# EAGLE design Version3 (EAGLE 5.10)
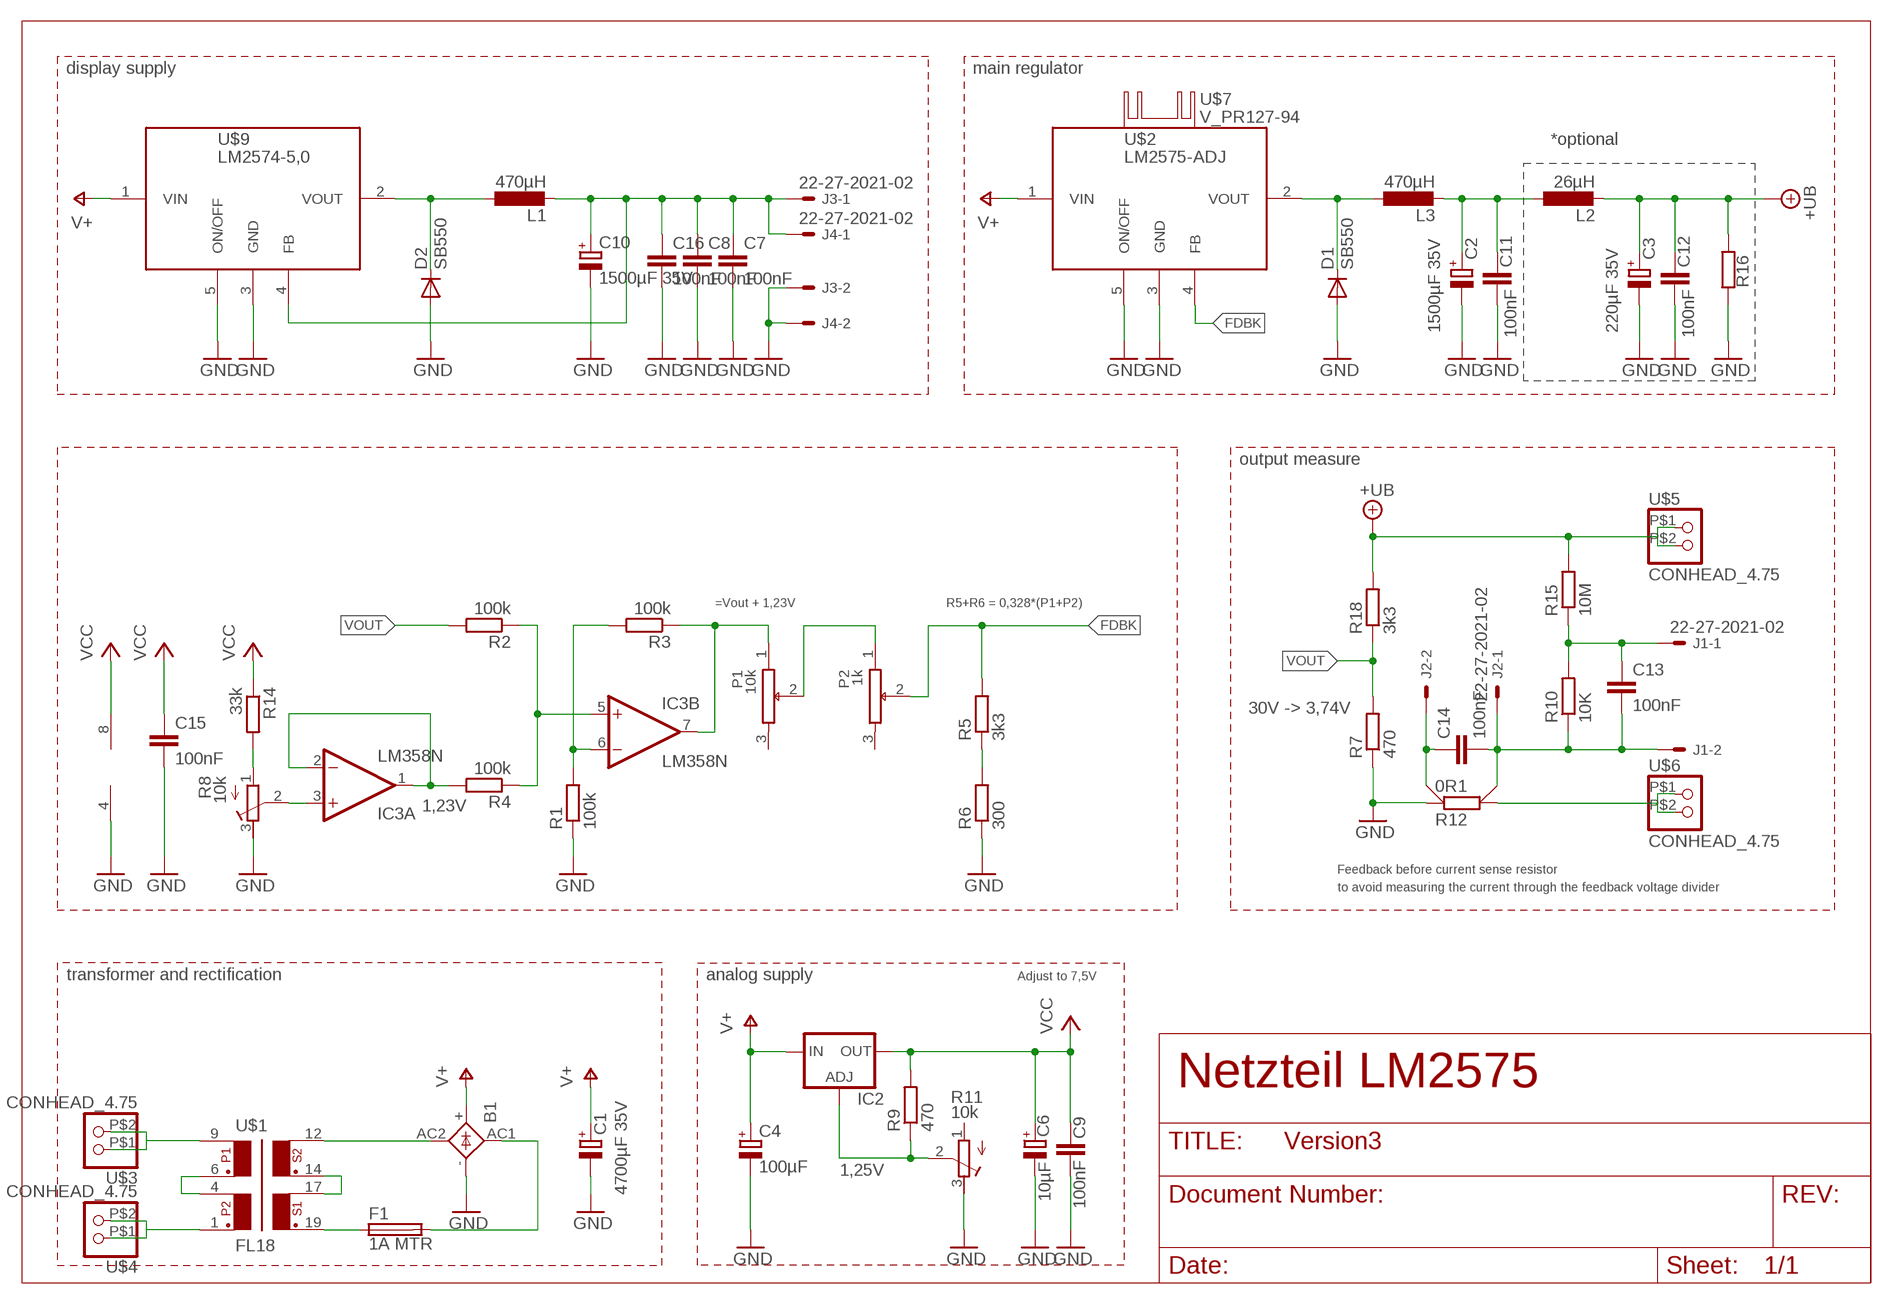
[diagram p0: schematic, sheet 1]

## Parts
B1  FB100  [FB100]
C1  4700µF 35V  CPOL-EUE7.5-18  [E7,5-18]
C2  1500µF 35V  CPOL-EUE5-13  [E5-13]
C3  220µF 35V  CPOL-EUE3.5-8  [E3,5-8]
C4  100µF  CPOL-EUE2.5-7  [E2,5-7]
C6  10µF  CPOL-EUE2-5  [E2-5]
C7  100nF  C-EU025-025X050  [C025-025X050]
C8  100nF  C-EU025-025X050  [C025-025X050]
C9  100nF  C-EU025-025X050  [C025-025X050]
C10  1500µF 35V  CPOL-EUE2.5-7  [E2,5-7]
C11  100nF  C-EU025-025X050  [C025-025X050]
C12  100nF  C-EU025-025X050  [C025-025X050]
C13  100nF  C-EU025-025X050  [C025-025X050]
C14  100nF  C-EU025-025X050  [C025-025X050]
C15  100nF  C-EU050-030X075  [C050-030X075]
C16  100nF  C-EU025-025X050  [C025-025X050]
D1  SB550  SB320  [DO201-15]
D2  SB550  SB320  [DO201-15]
F1  1A MTR  FUSESH22,5A  [SH22,5A]
IC2  LM317L  [317L]
IC3  LM358N  [DIL08]
J1  22-27-2021-02  [6410-02]
J2  22-27-2021-02  [6410-02]
J3  22-27-2021-02  [6410-02]
J4  22-27-2021-02  [6410-02]
L1  470µH  L-EUL-11PHC  [L-11PHC]
L2  26µH  L-EUFED26  [FED26]
L3  470µH  L-EUKM5  [INDUCTOR_KM5]
P1  10k  POTH_1  [POTH_1]
P2  1k  POTH_1  [POTH_1]
R1  100k  R-EU_0207/10_WP  [0207/10_WP]
R2  100k  R-EU_0207/10_WP  [0207/10_WP]
R3  100k  R-EU_0207/10_WP  [0207/10_WP]
R4  100k  R-EU_0207/10_WP  [0207/10_WP]
R5  3k3  R-EU_0207/10_WP  [0207/10_WP]
R6  300  R-EU_0207/10_WP  [0207/10_WP]
R7  470  R-EU_0207/10_WP  [0207/10_WP]
R8  10k  R-TRIMM64W  [RTRIM64W]
R9  470  R-EU_0207/10_WP  [0207/10_WP]
R10  10K  R-EU_0207/10_WP  [0207/10_WP]
R11  10k  R-TRIMM64W  [RTRIM64W]
R12  0R1  R_EU_S  [0617/22_D]
R14  33k  R-EU_0207/10_WP  [0207/10_WP]
R15  10M  R-EU_0207/10_WP  [0207/10_WP]
R16  R-EU_0309/12_WP  [0309/12_WP]
R18  3k3  R-EU_0207/10_WP  [0207/10_WP]
U$1  FL18  [FL18]
U$2  LM2575-ADJ  LM2575S  [TO220-51]
U$3  CONHEAD_4.75  [CONHEAD_4.75]
U$4  CONHEAD_4.75  [CONHEAD_4.75]
U$5  CONHEAD_4.75  [CONHEAD_4.75]
U$6  CONHEAD_4.75  [CONHEAD_4.75]
U$7  V_PR127-94  [V_PR127/94]
U$9  LM2574-5,0  LM2575S  [TO220-51]

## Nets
+UB: C3.+ C12.1 L2.P$2 R15.2 R16.2 R18.2 U$5.P$1 U$5.P$2
FDBK: P2.2 R5.2 U$2.4(FB)
GND: B1.- C1.- C2.- C3.- C4.- C6.- C7.2 C8.2 C9.2 C10.- C11.2 C12.2 C15.2 C16.2 D1.A D2.A IC3.4(P:V-) J3.2 J4.2 R1.1 R6.1 R7.1 R8.3(A) R11.3(A) R12.1 R16.1 U$2.3(GND) U$2.5(ON/OFF) U$9.3(GND) U$9.5(ON/OFF)
IN-: IC3.6(B:-IN) R1.2 R3.2
N$1: D1.C L3.P$1 U$2.2(VOUT)
N$2: F1.1 U$1.19
N$3: C2.+ C11.1 L2.P$1 L3.P$2
N$4: IC3.1(A:OUT) IC3.2(A:-IN) R4.2
N$5: D2.C L1.P$1 U$9.2(VOUT)
N$6: B1.AC1 F1.2
N$7: B1.AC2 U$1.12
N$8: U$1.4 U$1.6
N$9: U$1.14 U$1.17
N$10: U$1.9 U$3.P$1 U$3.P$2
N$11: U$1.1 U$4.P$1 U$4.P$2
N$12: P1.2 P2.1
N$13: R5.1 R6.2
N$14: IC3.5(B:+IN) R2.1 R4.1
N$15: R12.2 U$6.P$1 U$6.P$2
N$16: C13.1 J1.1 R10.2 R15.1
N$17: IC2.1(ADJ) R9.1 R11.2(S)
N$19: C13.2 C14.2 J1.2 J2.1 R10.1 R12.P$2
N$20: R8.1(E) R14.2
N$23: C14.1 J2.2 R12.P$1
N$24: IC3.7(B:OUT) P1.1 R3.1
N$31: C7.1 C8.1 C10.+ C16.1 J3.1 J4.1 L1.P$2 U$9.4(FB)
N$32: IC3.3(A:+IN) R8.2(S)
V+: B1.+ C1.+ C4.+ IC2.3(IN) U$2.1(VIN) U$9.1(VIN)
VCC: C6.+ C9.1 C15.1 IC2.2(OUT) IC3.8(P:V+) R9.2 R14.1
VOUT: R2.2 R7.2 R18.1
Unconnected: P1.3 P2.3 R11.1(E)

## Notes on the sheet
- display supply | main regulator
- *optional
- output measure
- =Vout + 1,23V | R5+R6 = 0,328*(P1+P2)
- 30V -> 3,74V
- 1,23V
- Feedback before current sense resistor
- to avoid measuring the current through the feedback voltage divider
- transformer and rectification | analog supply | Adjust to 7,5V
- Netzteil LM2575
- 1,25V

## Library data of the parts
B1 = rectifier:FB100: FAGOR RECTIFIER grid 1 x 10,2 x 7,5 mm
C1-C4 C6 C10 = rcl:CPOL-EU: POLARIZED CAPACITOR, European symbol
C7-C9 C11-C16 = rcl:C-EU: CAPACITOR, European symbol
D1 D2 = diode:SB320: DIODE
F1 = fuse:FUSE: Fuse
IC2 = v-reg:LM317L: VOLTAGE REGULATOR
IC3 = linear:LM358: OP AMP also LM158; LM258; LM2904 Source: http://cache.national.com/ds/LM/LM158.pdf
J1-J4 = con-molex:22-?-02: CONNECTOR
L1 = rcl2:L-EU: INDUCTOR, European symbol
L2 L3 = rcl:L-EU: INDUCTOR, European symbol
P1 P2 = Pot1:POTH_1
R1-R7 R9 R10 R14 R15 R18 = rcl:R-EU_: RESISTOR, European symbol
R8 R11 = rcl2:R-TRIMM: Trimm resistor
R12 = rcl2:R_EU_S
R16 = rcl2:R-EU_: RESISTOR, European symbol
U$1 = trafo:FL18: TRANSFORMER 2 primary winding, 2 secondary windings BLOCK
U$2 U$9 = linear2:LM2575
U$3-U$6 = pinhead:CONHEAD_4.75
U$7 = heatsink:V_PR127-94

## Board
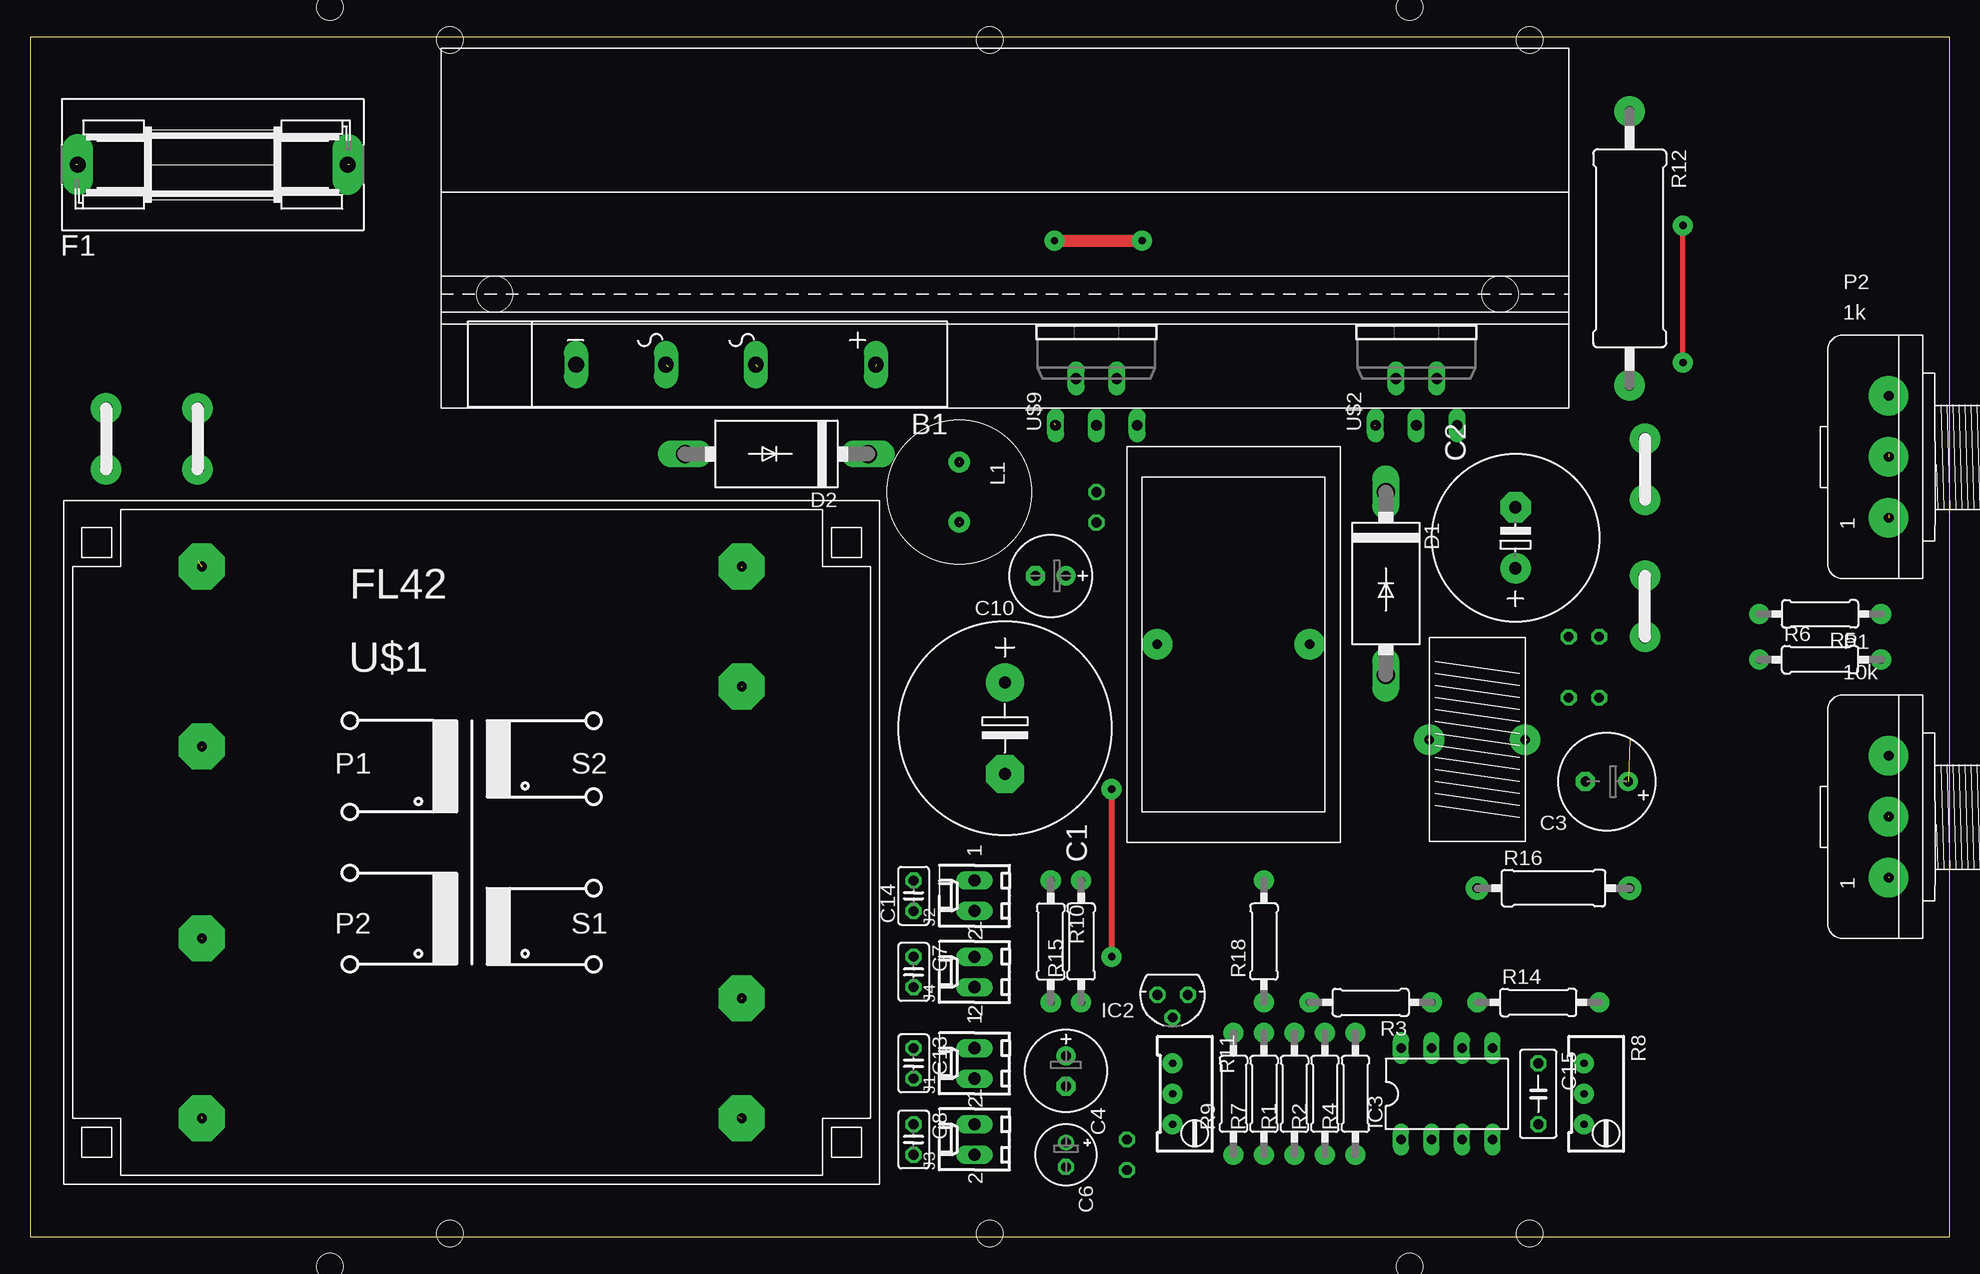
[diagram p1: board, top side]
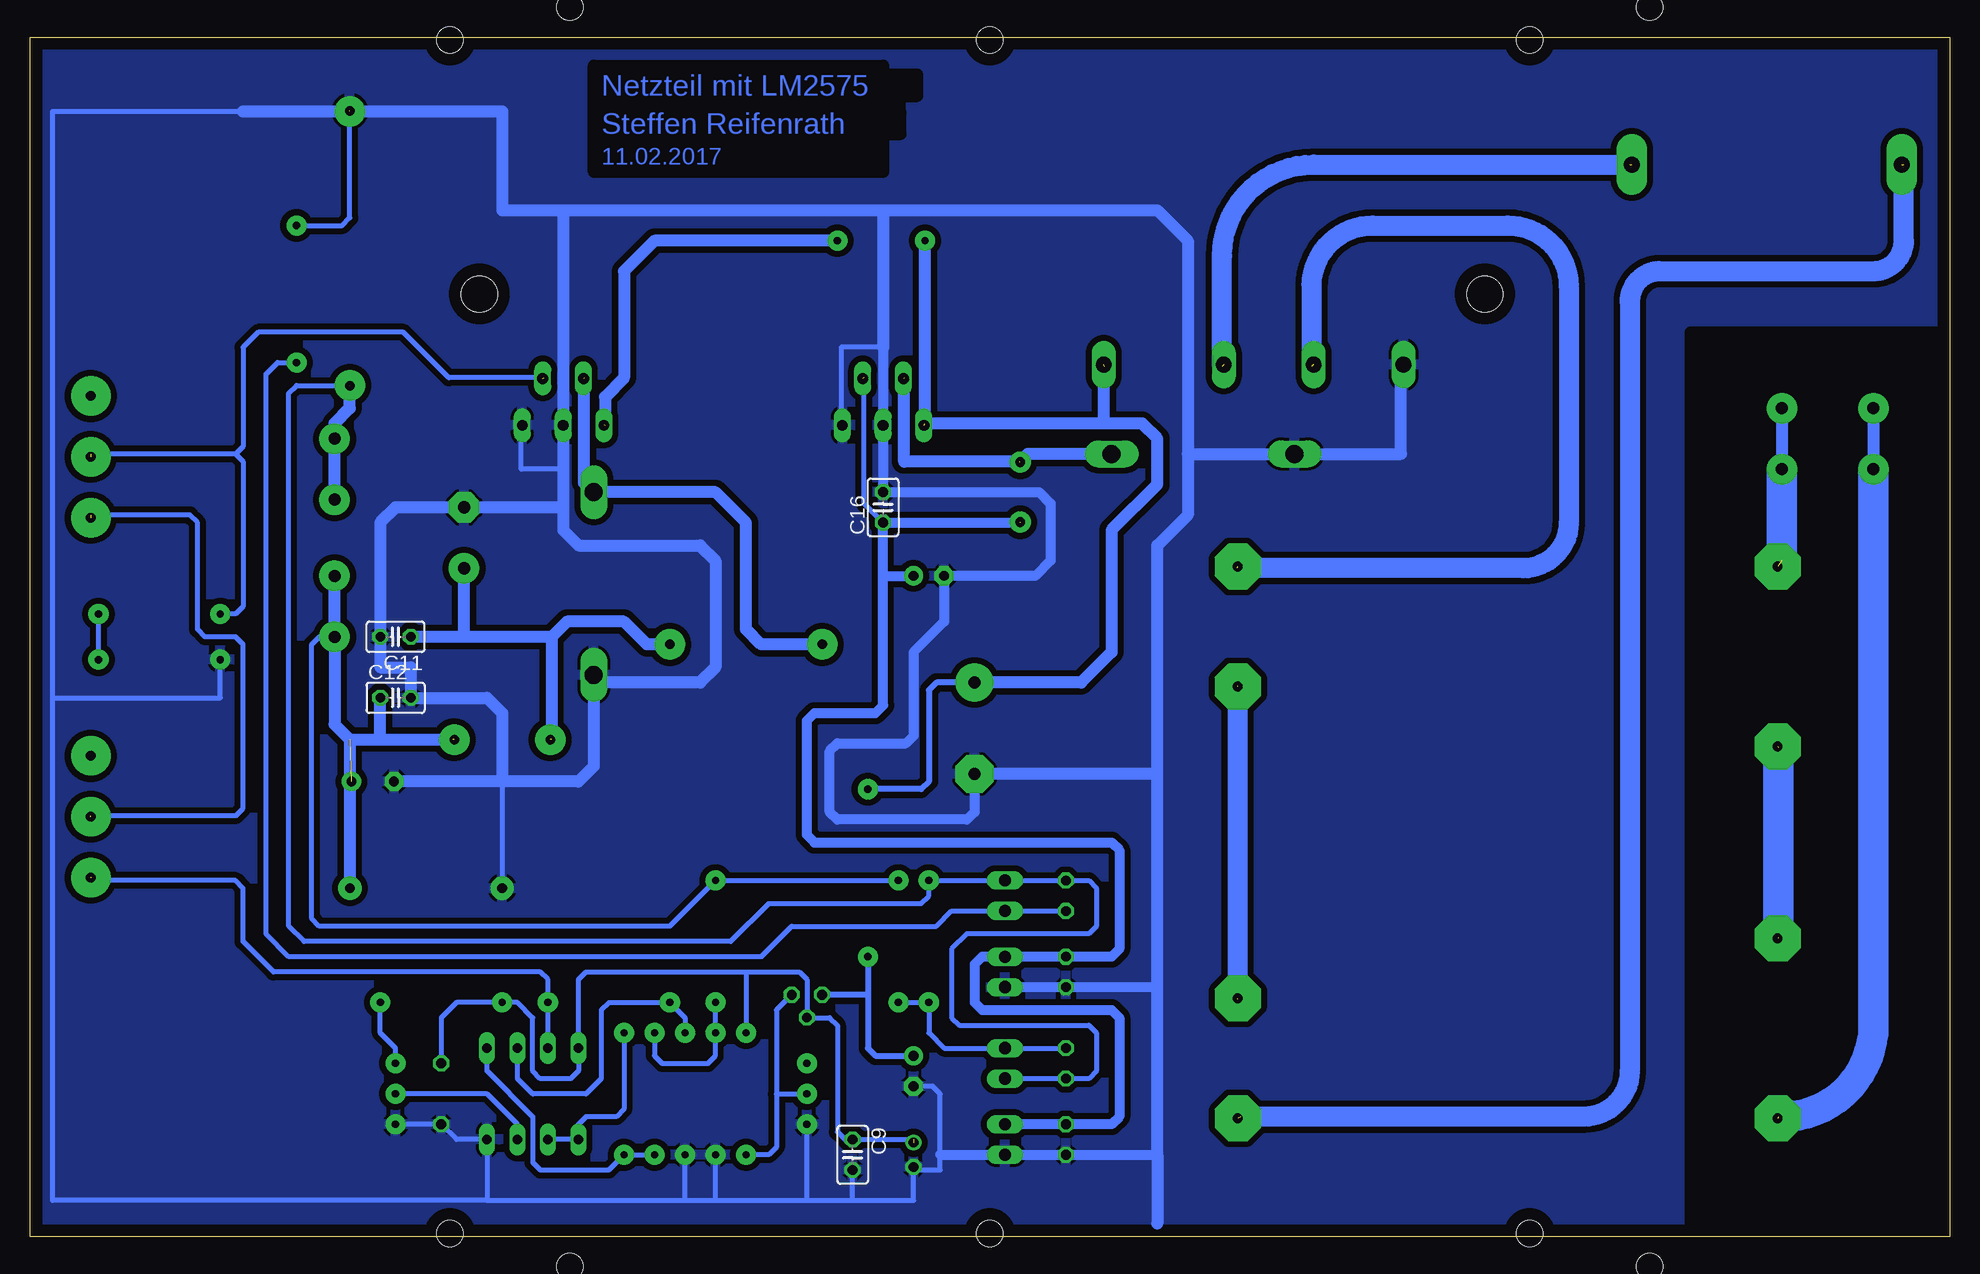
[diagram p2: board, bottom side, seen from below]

Size 160 x 100 mm. Coordinates in mm from the lower left corner, seen from the top.
Outline: 0,100 0,0 160,0 160,100 0,100
Copper layers (1*16): Top 0.035mm / dielectric 1.5mm / Bottom 0.035mm
Design rules "default": minimum track width 10mil, minimum drill 24mil, track to track 8mil, track to pad 8mil, pad to pad 8mil, via to via 8mil, smd to smd 8mil, copper to edge 40mil, drill to drill 8mil, minimum pad ring 10mil, minimum via ring 8mil, stop-mask expansion 4mil, vias tented up to drill 0mil, thermal gap 10mil
Holes 3 mm at 122.55,78.58 38.73,78.58
bRestrict: area 0,0.5 to 21.6,75.4; area 88.9,88.7 to 113,97.6

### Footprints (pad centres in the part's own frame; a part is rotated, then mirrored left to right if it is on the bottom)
FB100 = drill 1.321 long: + -14,0; - 10.994,0; AC1 -3.992,0; AC2 3.501,0
E7,5-18 = drill 1.016 pad 3.15 round: + -3.81,0 | drill 1.016 pad 3.15 octagon: - 3.81,0
E5-13 = drill 1.016 pad 2.54 round: + -2.54,0 | drill 1.016 pad 2.54 octagon: - 2.54,0
E3,5-8 = drill 0.813 pad 1.6 round: + -1.778,0 | drill 0.813 pad 1.6 octagon: - 1.778,0
E2,5-7 = drill 0.813 pad 1.6 round: + -1.27,0 | drill 0.813 pad 1.6 octagon: - 1.27,0
E2-5 = drill 0.813 pad 1.27 round: + -1.016,0 | drill 0.813 pad 1.27 octagon: - 1.016,0
C025-025X050 = drill 0.813 octagon: 1 -1.27,0; 2 1.27,0
C050-030X075 = drill 0.813 octagon: 1 -2.54,0; 2 2.54,0
DO201-15 = drill 1.499 long: A 7.62,0; C -7.62,0
SH22,5A = drill 1.321 pad 2.54 long: 1 -11.252,0; 2 11.252,0
317L = drill 0.813 octagon: 1 -1.27,0; 2 0,1.905; 3 1.27,0
DIL08 = drill 0.813 long: 1 -3.81,-3.81; 2 -1.27,-3.81; 3 1.27,-3.81; 4 3.81,-3.81; 5 3.81,3.81; 6 1.27,3.81; 7 -1.27,3.81; 8 -3.81,3.81
6410-02 = drill 1.016 long: 1 1.27,0; 2 -1.27,0
L-11PHC = drill 0.8 pad 1.778 round: P$1 -2.5,0; P$2 2.5,0
FED26 = drill 0.8 pad 2.54 round: P$1 0,4; P$2 0,-4
INDUCTOR_KM5 = drill 0.8 pad 2.54 round: P$1 0,6.35; P$2 0,-6.35
POTH_1 = drill 0.813 pad 3.302 round: 1 5.08,3.81; 2 0,3.81; 3 -5.08,3.81
0207/10_WP = drill 0.6 pad 1.676 round: 1 -5.08,0; 2 5.08,0
RTRIM64W = drill 0.61 pad 1.676 round: 1 1.27,-2.54; 2 1.27,0; 3 1.27,2.54
0617/22_D = drill 0.6 pad 2.54 round: 1 -11.43,0; 2 11.43,0 | drill 0.8 round: P$1 -11.455,0; P$2 11.455,0
0309/12_WP = drill 0.813 pad 1.93 round: 1 -6.35,0; 2 6.35,0
FL18 = drill 0.8 pad 3.81 octagon: 1 -22.5,-23; 4 -22.5,-8; 6 -22.5,8; 9 -22.5,23; 12 22.5,23; 14 22.5,13; 17 22.5,-13; 19 22.5,-23
TO220-51 = drill 0.9 long: 1 -3.4,-8.4; 2 -1.7,-4.5; 3 0,-8.4; 4 1.7,-4.5; 5 3.4,-8.4
CONHEAD_4.75 = drill 1 pad 2.54 round: P$1 -2.54,0; P$2 2.54,0
TEKO_KL = hole 2.2: 49.75,0; -49.75,0; -49.75,-45; 49.75,-45; 49.75,45; -49.75,45; 52.5,-55; -52.5,-55; -52.5,35; 52.5,35

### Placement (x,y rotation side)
B1  56.5,72.7 180 top
C1  81.27,42.38 270 top
C2  123.81,58.26 90 top
C3  131.44,37.94 180 top
C4  86.35,13.8 270 top
C6  86.35,6.82 270 top
C7  73.65,22.06 270 top
C8  73.65,8.09 270 top
C9  91.43,6.82 270 bottom
C10  85.08,55.08 180 top
C11  129.53,50 180 bottom
C12  129.53,44.92 0 bottom
C13  73.65,14.44 270 top
C14  73.65,28.41 90 top
C15  125.72,11.9 270 top
C16  88.89,60.8 90 bottom
D1  113.02,54.45 270 top
D2  62.22,65.24 180 top
F1  15.23,89.37 0 top
IC2  95.24,20.16 180 top
IC3  118.1,11.9 0 top
J1  78.73,14.44 90 top
J2  78.73,28.41 90 top
J3  78.73,8.09 90 top
J4  78.73,22.06 90 top
L1  77.46,62.06 270 top
L2  120.64,41.43 90 top
L3  100.32,49.37 90 top
P1  151.12,35 270 top
P2  151.12,65 270 top
R1  105.4,11.9 90 top
R2  107.94,11.9 90 top
R3  111.75,19.52 180 top
R4  110.48,11.9 90 top
R5  149.22,51.91 180 top
R6  149.22,48.09 0 top
R7  102.86,11.9 90 top
R8  130.8,11.9 180 top
R9  100.32,11.9 90 top
R10  85.08,24.6 270 top
R11  96.51,11.9 180 top
R12  133.34,82.38 270 top
R14  125.72,19.52 0 top
R15  87.62,24.6 90 top
R16  126.99,29.05 0 top
R18  102.86,24.6 90 top
U$1  36.82,32.86 0 top
U$2  115.56,76.03 0 top
U$3  13.96,66.51 270 top
U$4  6.34,66.51 270 top
U$5  134.61,52.54 90 top
U$6  134.61,63.97 270 top
U$7  34.28,69.05 0 top
U$8  [TEKO_KL]  80,50 270 top
U$9  88.89,76.03 0 top

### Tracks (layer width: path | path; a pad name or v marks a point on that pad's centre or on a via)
+UB  (2 unrouted)
  Bottom 0.406: R15.2 R18.2 106.67,25.87 135.88,25.87 136.51,26.5 136.51,49.37 135.88,50 U$5.P$1
  Bottom 1.016: 130.8,41.43 C12.1 | 130.8,41.43 124.77,41.43 | 133.34,41.43 130.8,41.43 | U$5.P$2 U$5.P$1 134.61,42.7 133.34,41.43 | 133.34,41.43 R16.2
FDBK  (2 unrouted)
  Bottom 0.406: 142.87,65.24 154.93,65.24 | 142.87,65.24 142.23,65.88 142.23,74.13 140.96,75.4 128.9,75.4 125.09,71.59 117.15,71.59 | 142.87,65.24 142.23,64.61 142.23,52.54 142.87,51.91 R5.2
GND
  Bottom 0.406: 92.38,67.78 92.38,74.13 88.89,74.13 | 142.23,93.81 158.11,93.81 158.11,44.92 | 158.11,44.92 158.11,3.01 121.91,3.01 | 121.91,3.01 105.4,3.01 | 105.4,3.01 102.86,3.01 | 102.86,3.01 95.24,3.01 | 95.24,3.01 91.43,3.01 | 91.43,3.01 86.35,3.01 86.35,5.55 84.13,5.55 84.13,6.82 84.13,11.9 84.76,12.53 C4.- | 121.91,3.01 IC3.4 124.45,8.09 C15.2 R8.3 | 102.86,3.01 R7.1 | 105.4,3.01 R1.1 | 95.24,3.01 R11.3 | 119.05,67.78 119.05,63.97 115.56,63.97 | 120.64,37.94 R16.1 | R6.1 144.13,44.92 158.11,44.92 | 91.43,3.01 C9.2
  Bottom 0.813: 66.03,6.82 C8.2 J3.2 84.13,6.82 | J4.2 C7.2 66.03,20.79 | 88.89,74.13 C16.2 75.87,62.06 74.92,61.11 74.92,56.35 76.19,55.08 C10.- 83.81,51.27 86.35,48.73 86.35,41.74 86.98,41.11 92.7,41.11 93.34,40.48 93.34,35.39 92.7,34.76 81.91,34.76 81.27,35.39 C1.-
  Bottom 1.016: 45.71,72.54 45.71,65.24 D2.A 63.49,65.24 | 63.49,65.24 63.49,60.16 66.03,57.62 66.03,38.57 | 63.49,65.24 63.49,83.02 66.03,85.56 88.89,85.56 | 88.89,85.56 88.89,74.13 | 66.03,38.57 C1.- | 115.56,85.56 88.89,85.56 | 115.56,85.56 120.64,85.56 120.64,93.81 R12.1 142.23,93.81 | 115.56,60.8 115.56,63.97 115.56,85.56 | 66.03,38.57 66.03,20.79 66.03,6.82 66.03,1.1 | 115.56,60.8 C2.- 129.53,60.8 130.8,59.52 C11.2 130.8,47.46 128.26,47.46 C12.2 121.91,44.92 120.64,43.65 120.64,37.94 | 115.56,60.8 115.56,58.89 114.29,57.62 104.13,57.62 102.86,56.35 102.86,47.46 104.13,46.19 113.02,46.19 | 120.64,37.94 114.29,37.94 113.02,39.2 113.02,46.19 | 120.64,37.94 129.85,37.94 | 113.02,46.19 D1.A
  pour Bottom (isolate 0.508): -1.28,-0.8 161.28,-0.8 161.28,100.8 -1.28,100.8
IN-
  Bottom 0.406: IC3.6 119.37,13.17 118.1,11.9 113.66,11.9 112.38,13.17 112.38,18.89 111.75,19.52 R3.2 105.4,18.25 R1.2
N$1  (1 unrouted)
  Bottom 1.016: 113.81,71.59 113.81,62.86 D1.C 102.86,62.06 100.32,59.52 100.32,50.63 99.05,49.37 L3.P$1
N$2  (2 unrouted)
  Bottom 1.676: 59.05,9.99 30.47,9.99 arc-90 26.66,13.8 26.66,77.94 arc90 24.12,80.48 6.34,80.48 arc-90 3.8,83.02 3.8,89.37
N$3  (1 unrouted)
  Bottom 1.016: L3.P$2 108.58,49.37 110.48,51.27 115.24,51.27 116.51,50 | 116.51,50 116.51,41.43 117.15,41.43 | 123.81,50 C2.+ | 123.81,50 C11.1 | 116.51,50 123.81,50
N$4
  Bottom 0.406: R4.2 110.48,10.63 111.11,9.99 113.66,9.99 114.29,9.36 IC3.1 IC3.2
N$5  (2 unrouted)
  Bottom 1.016: 87.14,71.59 87.14,64.61 77.46,64.61 76.83,65.24 D2.C
N$6  (2 unrouted)
  Bottom 1.676: 26.66,89.37 53.01,89.37 arc-90 60.63,81.75 60.63,72.54
N$7  (2 unrouted)
  Bottom 1.676: 59.36,55.72 35.55,55.72 arc-90 31.74,59.52 31.74,79.21 arc-90 36.82,84.29 48.09,84.29 arc-90 53.17,79.21 53.17,72.54
N$8  (2 unrouted)
  Bottom 2.54: 14.28,40.79 14.28,24.92
N$9  (2 unrouted)
  Bottom 1.676: 59.36,45.87 59.36,19.84
N$10  (1 unrouted)
  Bottom 1.016: U$3.P$1 U$3.P$2
  Bottom 2.54: U$3.P$2 13.96,56.35
N$11  (1 unrouted)
  Bottom 1.016: U$4.P$1 U$4.P$2
  Bottom 2.54: U$4.P$2 6.34,17.62 arc90 13.96,9.99 | 13.96,9.99 14.28,9.99 | 13.96,9.99 14.59,9.99
N$12  (2 unrouted)
  Bottom 0.406: 154.93,60.16 146.68,60.16 146.04,59.52 146.04,50.63 145.41,50 142.87,50 142.23,49.37 142.23,35.71 142.87,35.08 154.93,35.08
N$13
  Bottom 0.406: R5.1 R6.2
N$14
  Bottom 0.406: R2.1 R4.1 111.75,5.55 117.47,5.55 118.1,6.19 118.1,9.99 121.91,13.8 IC3.5
N$15
  Bottom 1.016: R12.2 133.34,69.05 134.61,67.78 U$6.P$1 U$6.P$2
N$16
  Bottom 0.406: C13.1 J1.1 83.81,15.71 85.08,16.98 R10.2 R15.1
N$17
  Bottom 0.406: IC2.1 97.78,18.89 97.78,11.9 | 97.78,11.9 R11.2 | 97.78,11.9 97.78,7.45 98.41,6.82 R9.1
N$19  (1 unrouted)
  Bottom 0.406: 133.34,70.95 137.78,70.95 138.42,70.32 138.42,25.87 137.15,24.6 101.59,24.6 98.41,27.77 85.72,27.77 85.08,28.41 R10.1 J2.1 C14.2 71.75,29.68 71.11,29.05 71.11,25.87 71.75,25.23 81.91,25.23 83.17,23.96 83.17,18.25 82.54,17.62 71.75,17.62 71.11,16.98 71.11,13.8 71.75,13.17 C13.2 J1.2
N$20
  Bottom 0.406: R14.2 130.8,16.98 129.53,15.71 R8.1
N$21  (via drill 0.6 pad 1.68)
  other vias: 35,99.75
N$22  (via drill 0.6 pad 1.68)
  other vias: 80,99.75
N$23  (via drill 0.6 pad 1.68)  (1 unrouted)
  Top 0.406: v137.78,72.86 v137.78,84.29
  Bottom 0.406: v137.78,84.29 133.97,84.29 133.34,84.92 133.34,93.81 | C14.1 J2.2 83.17,27.14 84.44,25.87 96.51,25.87 99.05,23.33 138.42,23.33 140.32,25.23 140.32,71.91 139.37,72.86 v137.78,72.86
N$24  (1 unrouted)
  Bottom 0.406: 154.93,30 154.93,29.68 142.87,29.68 142.23,29.05 142.23,24.6 139.69,22.06 117.47,22.06 116.83,21.43 R3.1 IC3.7
N$25  (via drill 0.6 pad 1.68)
  other vias: 125,99.75
N$26  (via drill 0.6 pad 1.68)
  other vias: 35,0.25
N$27  (via drill 0.6 pad 1.68)
  other vias: 80,0.25
N$28  (via drill 0.6 pad 1.68)
  other vias: 125,0.25
N$29  (via drill 0.6 pad 1.68)
  other vias: 38.73,78.58
N$30  (via drill 0.6 pad 1.68)
  other vias: 122.55,78.58
N$31  (2 unrouted)
  Bottom 0.406: C16.1 90.48,61.11 90.48,71.59
  Bottom 0.813: 77.46,59.52 C16.1 88.89,55.08 | J3.1 C8.1 69.84,9.36 69.2,9.99 69.2,18.25 69.84,18.89 80.64,18.89 81.27,19.52 81.27,22.7 80.64,23.33 J4.1 C7.1 69.84,23.33 69.2,23.96 69.2,32.22 69.84,32.86 94.61,32.86 95.24,33.49 95.24,43.02 94.61,43.65 89.53,43.65 88.89,44.28 88.89,55.08 | 88.89,55.08 C10.+
N$32
  Bottom 0.406: IC3.3 119.37,9.36 121.91,11.9 R8.2
V+  (via drill 0.6 pad 1.68)  (3 unrouted)
  Top 0.508: v90.16,37.3 v90.16,23.33
  Top 1.016: v85.4,83.02 v92.7,83.02
  Bottom 0.508: C1.+ 84.44,46.19 85.08,45.55 85.08,37.94 85.72,37.3 v90.16,37.3 | v90.16,23.33 90.16,20.16 | 90.16,20.16 IC2.3 | C4.+ 89.53,15.08 90.16,15.71 90.16,20.16
  Bottom 1.016: 85.4,67.78 85.4,67.46 | C1.+ 72.38,46.19 69.84,48.73 69.84,58.89 66.03,62.7 66.03,66.51 67.3,67.78 70.47,67.78 | 85.4,67.78 v85.4,83.02 | v92.7,83.02 107.94,83.02 110.48,80.48 110.48,71.59 112.07,70 112.07,67.62 | 70.47,67.78 85.4,67.78 | 70.47,67.78 70.47,72.54
VCC  (1 unrouted)
  Bottom 0.406: C15.1 125.72,18.25 124.45,19.52 R14.1 119.37,19.52 118.1,18.25 118.1,13.8 117.47,13.17 114.92,13.17 114.29,13.8 IC3.8 114.29,21.43 113.66,22.06 100.32,22.06 | 100.32,22.06 95.88,22.06 95.24,21.43 IC2.2 93.34,18.25 92.7,17.62 92.7,8.73 92.06,8.09 C9.1 86.35,8.09 | 100.32,22.06 R9.2
VOUT
  Bottom 0.406: R18.1 R7.2 102.86,15.08 103.5,14.44 107.31,14.44 107.94,15.08 R2.2

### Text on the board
Bottom: Netzteil mit LM2575 | Steffen Reifenrath | 11.02.2017
tTest: TP2 | TP1 | TP3 | TP4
